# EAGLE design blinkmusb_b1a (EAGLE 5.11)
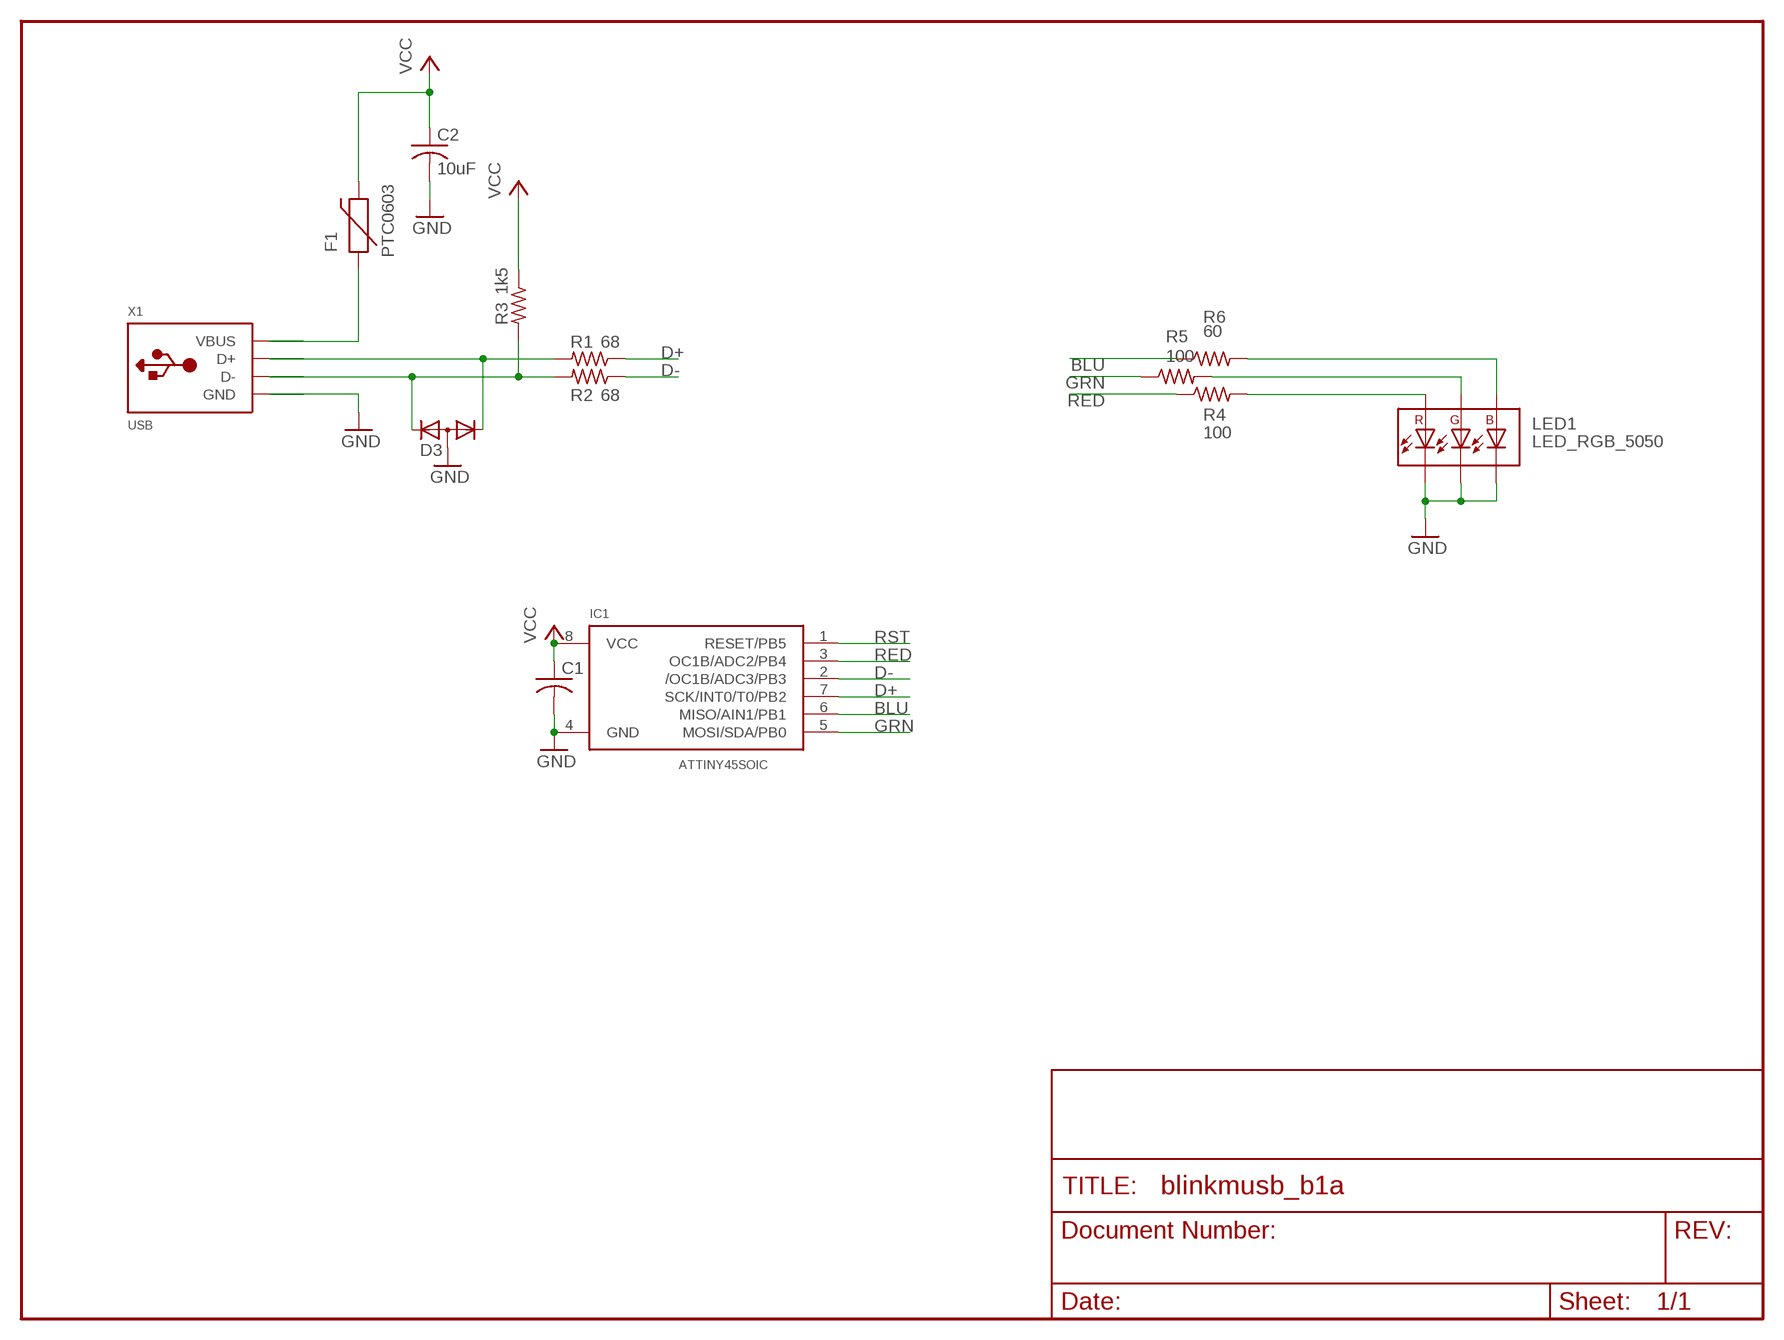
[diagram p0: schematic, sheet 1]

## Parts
C1  C-USC0603  [C0603]
C2  10uF  C-USC0805  [C0805]
D3  DIODE-2CA|ACSOT23  [SOT23]
F1  PTC0603  [0603]
IC1  ATTINY45SOIC  [SO08-EIAJ]
LED1  LED_RGB_5050  [LED_5050]
R1  68  R-US_R0603  [R0603]
R2  68  R-US_R0603  [R0603]
R3  1k5  R-US_R0603  [R0603]
R4  100  R-US_R0603  [R0603]
R5  100  R-US_R0603  [R0603]
R6  60  R-US_R0603  [R0603]
X1  USB  [MOLEX-48037-1000]

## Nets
BLU: IC1.6(MISO/AIN1/PB1) R6.1
D+: IC1.7(SCK/INT0/T0/PB2) R1.1
D-: IC1.2(/OC1B/ADC3/PB3) R2.1
GND: C1.2 C2.2 D3.3(A) IC1.4(GND) LED1.P$4(C2) LED1.P$5(C1) LED1.P$6(C0) X1.4(GND)
GRN: IC1.5(MOSI/SDA/PB0) R5.1
N$4: D3.1(K1) R1.2 X1.3(D+)
N$5: D3.2(K2) R2.2 R3.2 X1.2(D-)
N$13: F1.1 X1.1(VBUS)
RBLU: LED1.P$3(A2) R6.2
RED: IC1.3(OC1B/ADC2/PB4) R4.1
RGRN: LED1.P$2(A1) R5.2
RRED: LED1.P$1(A0) R4.2
RST: IC1.1(RESET/PB5)
VCC: C1.1 C2.1 F1.2 IC1.8(VCC) R3.1

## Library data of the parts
C1 C2 = rcl:C-US: CAPACITOR, American symbol
D3 = diode:DIODE-2CA|AC: Dual DIODE Cathode-Anode|Anode-Cathode
F1 = SparkFun-20110517:PTC: Resettable Fuse PTC
IC1 = todstuff:ATTINY45
LED1 = todstuff:LED_RGB_5050
R1-R6 = rcl:R-US_: RESISTOR, American symbol
X1 = todstuff:USB

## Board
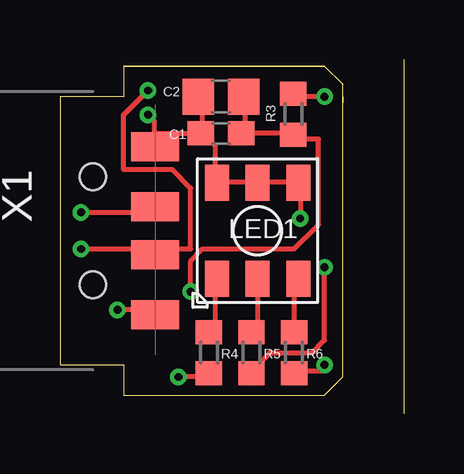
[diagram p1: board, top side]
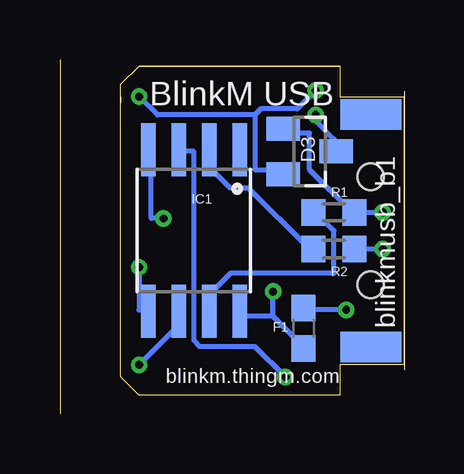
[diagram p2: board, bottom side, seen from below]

Size 14.34 x 14.73 mm. Coordinates in mm from the lower left corner, seen from the top.
Outline: 2.66,0.76 2.66,2.03 0,2.03 0,13.21 2.66,13.21 2.66,14.48
Outline: 2.66,0.76 10.53,0.76 10.78,0.76 11.04,0.76
Outline: 11.8,1.52 11.8,1.78 11.8,2.29
Outline: 11.8,2.29 11.8,12.95
Outline: 11.8,12.95 11.8,13.46 11.8,13.72
Outline: 11.04,14.48 10.78,14.48 10.53,14.48 2.66,14.48
Outline: 11.8,2.03 11.8,2.29
Outline: 11.8,13.21 11.8,12.95
Outline: 14.34,14.73 14.34,0
Outline: 11.04,14.48 11.8,13.72
Outline: 11.04,0.76 11.8,1.52
Outline: 2.66,14.48 11.04,14.48
Outline: 2.66,0.76 11.04,0.76
Outline: 11.8,1.52 11.8,13.72
Copper layers (1*16): Top 0.0356mm / dielectric 1.5011mm / Bottom 0.0356mm
Design rules "LaenPCBOrder *": minimum track width 8mil, minimum drill 13mil, track to track 6mil, track to pad 8mil, pad to pad 8mil, via to via 8mil, smd to smd 6mil, copper to edge 15mil, drill to drill 8mil, minimum pad ring 7mil, minimum via ring 7mil, stop-mask expansion 4mil, vias tented up to drill 25mil, thermal gap 10mil

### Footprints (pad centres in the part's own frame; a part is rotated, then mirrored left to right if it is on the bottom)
C0603 = smd 1.1 x 1: 1 -0.85,0; 2 0.85,0
C0805 = smd 1.3 x 1.5: 1 -0.95,0; 2 0.95,0
SOT23 = smd 1 x 1.4: 1 -0.95,-1.1; 2 0.95,-1.1; 3 0,1.1
0603 = smd 1.1 x 1: 1 -0.85,0; 2 0.85,0
SO08-EIAJ = smd 0.61 x 2.21: 1 -1.905,-3.378; 2 -0.635,-3.378; 3 0.635,-3.378; 4 1.905,-3.378; 5 1.905,3.353; 6 0.635,3.353; 7 -0.635,3.353; 8 -1.905,3.353
LED_5050 = smd 1 x 1.5: P$1 1.7,2; P$2 0,2; P$3 -1.7,2; P$4 -1.7,-2; P$5 0,-2; P$6 1.7,-2
R0603 = smd 1 x 1.1: 1 -0.85,0; 2 0.85,0
MOLEX-48037-1000 = smd 2 x 1.2: 1 2.6,-3.5; 2 2.6,-1; 3 2.6,1; 4 2.6,3.5 | smd 2.54 x 1.27 bottom: P$1 0,4.85; P$2 0,-4.85 | hole 1.1: 0,2.25; 0,-2.25

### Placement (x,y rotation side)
C1  6.72,11.68 180 top
C2  6.72,13.21 180 top
D3  3.93,10.92 270 bottom
F1  4.18,3.56 270 bottom
IC1  8.75,7.62 180 bottom
LED1  8.24,7.62 180 top
R1  2.91,8.38 0 bottom
R2  2.91,6.86 0 bottom
R3  9.74,12.48 90 top
R4  6.21,2.54 90 top
R5  7.99,2.54 90 top
R6  9.77,2.54 90 top
X1  1.38,7.62 0 top

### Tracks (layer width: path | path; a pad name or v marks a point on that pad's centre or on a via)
BLU  (via drill 0.33)
  Top 0.203: v11.04,2.03 11.04,1.78 9.77,1.78 R6.1
  Bottom 0.203: v11.04,2.03 9.51,3.56 9.51,4.06 IC1.6
D+
  Bottom 0.203: R1.1 3.67,8.38 2.91,7.62 2.91,5.84 7.23,5.84 7.99,5.08 7.99,4.32 IC1.7
D-
  Bottom 0.203: R2.1 3.93,6.86 6.47,9.4 7.23,9.4 7.99,10.16 7.99,10.92 IC1.2
GND  (via drill 0.33)
  Top 0.203: 5.96,11.68 5.96,13.21 C2.2 | C1.2 5.96,11.68 | v3.67,12.45 3.93,12.19 3.93,11.68 | 3.93,11.68 3.93,11.18 X1.4 3.93,11.68 | 3.93,11.68 5.7,11.68 C1.2 | 8.24,9.65 6.72,9.65 LED1.P$6 6.47,9.65 6.47,11.18 5.96,11.68 | 8.24,9.65 LED1.P$5 8.24,9.65 | 8.24,9.65 9.77,9.65 LED1.P$4 10.02,9.4 v10.02,8.13 | C1.2 5.96,11.68
  Bottom 0.203: v3.67,12.45 3.67,12.19 2.91,11.43 2.91,10.92 D3.3 | v10.02,8.13 10.53,8.13 10.53,10.92 IC1.4
GRN  (via drill 0.33)
  Top 0.203: v11.04,6.1 11.04,3.05 10.53,2.54 8.75,2.54 7.99,1.78 R5.1
  Bottom 0.203: v11.04,6.1 11.04,4.32 10.78,4.32 IC1.5
N$4  (via drill 0.33)
  Top 0.203: v0.88,8.38 3.93,8.38 X1.3
  Bottom 0.203: D3.1 4.94,11.68 3.93,11.68 3.93,10.16 2.15,8.38 R1.2 1.89,8.38 v0.88,8.38
N$5  (via drill 0.33)
  Top 0.203: v0.88,6.86 3.93,6.86 X1.2 4.18,6.86 5.45,6.86 5.45,9.4 4.69,10.16 2.66,10.16 2.66,12.45 v3.67,13.46 | v11.04,13.21 9.77,13.21 R3.2
  Bottom 0.203: v0.88,6.86 1.89,6.86 R2.2 | v11.04,13.21 10.28,12.45 6.21,12.45 | 6.21,12.45 6.21,10.16 5.2,10.16 D3.2 | v3.67,13.46 4.43,12.7 5.96,12.7 6.21,12.45
N$13  (via drill 0.33)
  Top 0.203: v2.4,4.32 3.93,4.32 X1.1
  Bottom 0.203: v2.4,4.32 4.18,4.32 F1.1
RBLU
  Top 0.203: R6.2 9.77,3.56 9.77,5.59 LED1.P$3
RED  (via drill 0.33)
  Top 0.203: v4.94,1.52 6.21,1.52 R4.1
  Bottom 0.203: v4.94,1.52 6.21,2.79 8.5,2.79 8.75,3.05 8.75,10.92 9.26,10.92 IC1.3
RGRN
  Top 0.203: R5.2 7.99,3.56 8.24,3.81 8.24,5.59 LED1.P$2
RRED
  Top 0.203: R4.2 6.21,3.56 6.47,3.81 6.47,5.59 LED1.P$1
VCC  (via drill 0.33)
  Top 0.203: 7.74,11.68 7.74,13.21 C2.1 | 7.74,11.68 C1.1 7.74,11.68 | 7.74,11.68 9.51,11.68 R3.1 9.77,11.43 10.78,11.43 10.78,7.87 9.77,6.86 5.96,6.86 5.45,6.35 v5.45,5.08
  Bottom 0.203: 5.45,4.06 4.18,2.79 F1.2 | 5.45,4.06 6.72,4.06 IC1.8 | 5.45,4.06 v5.45,5.08

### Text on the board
bPlace: BlinkM USB | blinkmusb_b1 | blinkm.thingm.com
